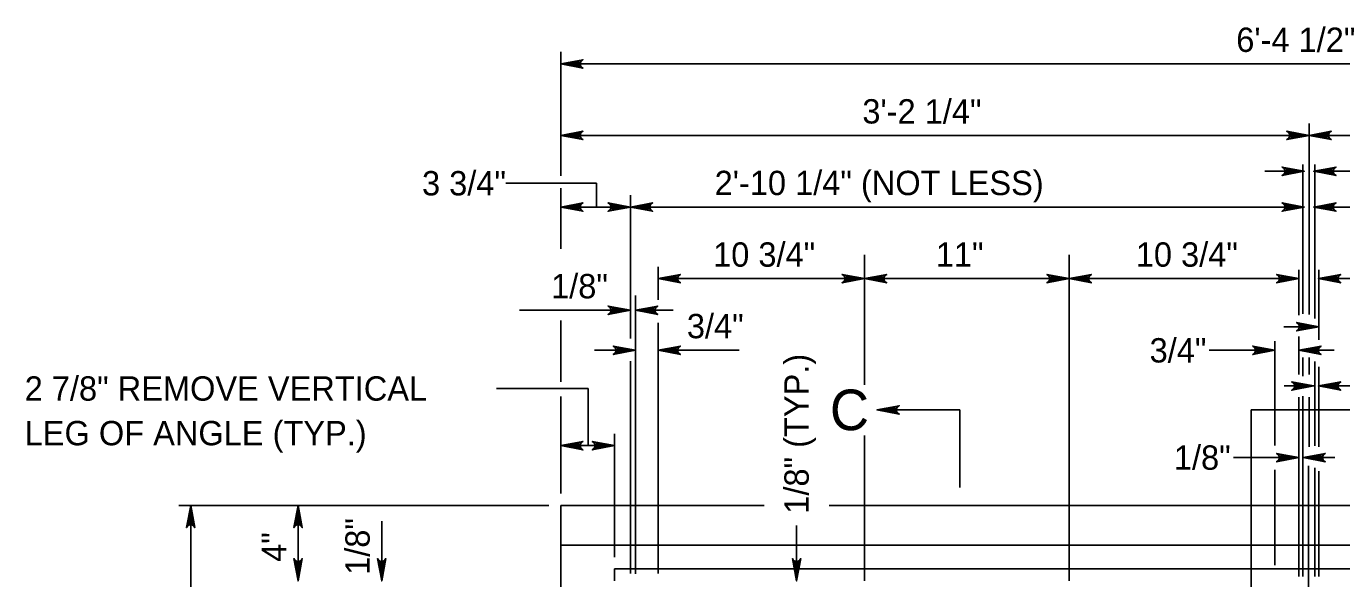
# Model space of a CAD drawing. Extents: x 0.7 to 7.67, y -7.49 to 2.47.
# Drawn here: x 0.71 to 3.951, y 1.111 to 2.473 of the extents above; entities that cross this region are included whole.
import ezdxf

# ---------------------------------------------------------------- set-up
doc = ezdxf.new("R2010")
doc.units = 0
for name, color, linetype in [('DETL-DIMS', 7, 'Continuous'), ('DETL-LINE', 7, 'Continuous'), ('DETL-NOTE', 7, 'Continuous'), ('DETL-TITL', 7, 'Continuous')]:
    doc.layers.add(name, color=color, linetype=linetype)

msp = doc.modelspace()

# ---------------------------------------------------------------- linework, layer by layer
at = {"layer": 'DETL-DIMS'}
for p, q in [((2.0269, 2.1048), (2.0269, 2.4099)), ((2.0269, 2.3805), (5.7132, 2.3805)), ((3.8707, 2.204), (2.0269, 2.204)), ((3.8707, 1.7626), (3.8707, 2.2334)), ((3.8707, 2.204), (5.7132, 2.204)), ((3.7617, 2.1158), (3.8554, 2.1158)), ((3.8554, 1.7642), (3.8554, 2.1326)), ((3.8848, 1.7527), (3.8848, 2.1326)), ((3.8848, 2.1158), (4.0025, 2.1158)), ((2.1153, 2.0862), (1.8921, 2.0862)), ((2.1153, 2.0262), (2.1153, 2.0862)), ((2.0269, 1.9249), (2.0269, 2.0739)), ((2.1985, 1.7038), (2.1985, 2.0569)), ((2.0269, 2.0275), (3.8554, 2.0275)), ((3.8848, 2.0275), (5.7132, 2.0275)), ((2.2671, 1.7984), (2.2671, 1.8805)), ((2.7751, 1.5889), (2.7751, 1.9099)), ((3.2796, 1.106), (3.2796, 1.9099)), ((2.7751, 1.8511), (2.2671, 1.8511)), ((2.7751, 1.8511), (3.2796, 1.8511)), ((3.2796, 1.8511), (3.8455, 1.8511)), ((3.8455, 1.7609), (3.8455, 1.8726)), ((3.8946, 1.7004), (3.8946, 1.8726)), ((4.4594, 1.8511), (3.8946, 1.8511)), ((2.2112, 1.1236), (2.2112, 1.8097)), ((2.1985, 1.7731), (1.9254, 1.7731)), ((2.2112, 1.7731), (2.3039, 1.7731)), ((2.0269, 1.597), (2.0269, 1.7478)), ((2.2671, 1.1245), (2.2671, 1.7422)), ((3.8946, 1.7325), (3.8087, 1.7325)), ((3.7867, 1.4396), (3.7867, 1.6972)), ((3.8455, 1.6151), (3.8455, 1.7086)), ((2.1101, 1.6746), (2.2112, 1.6746)), ((2.2671, 1.6746), (2.4669, 1.6748)), ((3.7867, 1.6743), (3.6247, 1.6743)), ((3.8455, 1.6743), (3.9328, 1.6743)), ((3.8554, 1.6109), (3.8554, 1.6563)), ((3.8707, 1.6151), (3.8707, 1.6563)), ((2.1985, 1.1245), (2.1985, 1.6476)), ((3.8848, 1.4386), (3.8848, 1.6465)), ((3.8946, 1.4365), (3.8946, 1.6334)), ((2.0942, 1.5802), (1.8688, 1.5802)), ((2.0269, 1.3217), (2.0269, 1.5605)), ((2.0942, 1.4389), (2.0942, 1.5802)), ((3.8095, 1.5864), (3.8828, 1.5864)), ((3.8455, 1.1166), (3.8455, 1.559)), ((3.8554, 1.1166), (3.8554, 1.5611)), ((3.8707, 1.4365), (3.8707, 1.559)), ((3.8939, 1.5864), (4.0308, 1.5864)), ((2.8061, 1.5275), (3.0104, 1.5275)), ((3.0104, 1.3364), (3.0104, 1.5275)), ((2.1593, 1.1648), (2.1593, 1.4687)), ((2.7751, 1.106), (2.7751, 1.4641)), ((2.0269, 1.4393), (2.1593, 1.4393)), ((3.8455, 1.1166), (3.8455, 1.4302)), ((3.6845, 1.4099), (3.8454, 1.4099)), ((3.8558, 1.4099), (3.9345, 1.4099)), ((3.7867, 1.1446), (3.7867, 1.3794)), ((3.8693, 1.3894), (3.8693, -0.7657)), ((3.8848, 1.1166), (3.8848, 1.3846)), ((3.8946, 1.1166), (3.8946, 1.3762)), ((1.9975, 1.2922), (1.0858, 1.2922)), ((1.1152, -0.5901), (1.1152, 1.2922)), ((1.3799, 1.106), (1.3799, 1.2922)), ((1.5858, 1.106), (1.5858, 1.253)), ((2.608, 1.2422), (2.608, 1.106))]:
    msp.add_line(p, q, dxfattribs=at)
for points in [[(2.0269, 2.3805), (2.0818, 2.3908), (2.0775, 2.3878), (2.0754, 2.3842), (2.0747, 2.3805), (2.0754, 2.3768), (2.0775, 2.3731), (2.0818, 2.3702), (2.0269, 2.3805), (2.0775, 2.3731), (2.0754, 2.3768), (2.0269, 2.3805), (2.0747, 2.3805), (2.0754, 2.3842), (2.0269, 2.3805), (2.0775, 2.3878)], [(2.0269, 2.204), (2.0818, 2.2143), (2.0775, 2.2114), (2.0754, 2.2077), (2.0747, 2.204), (2.0754, 2.2003), (2.0775, 2.1967), (2.0818, 2.1937), (2.0269, 2.204), (2.0775, 2.1967), (2.0754, 2.2003), (2.0269, 2.204), (2.0747, 2.204), (2.0754, 2.2077), (2.0269, 2.204), (2.0775, 2.2114)], [(3.8707, 2.204), (3.8159, 2.1937), (3.8201, 2.1967), (3.8223, 2.2003), (3.8229, 2.204), (3.8223, 2.2077), (3.8201, 2.2114), (3.8159, 2.2143), (3.8707, 2.204), (3.8201, 2.2114), (3.8223, 2.2077), (3.8707, 2.204), (3.8229, 2.204), (3.8223, 2.2003), (3.8707, 2.204), (3.8201, 2.1967)], [(3.8707, 2.204), (3.9255, 2.1937), (3.9213, 2.1967), (3.9191, 2.2003), (3.9185, 2.204), (3.9191, 2.2077), (3.9213, 2.2114), (3.9255, 2.2143), (3.8707, 2.204), (3.9213, 2.2114), (3.9191, 2.2077), (3.8707, 2.204), (3.9185, 2.204), (3.9191, 2.2003), (3.8707, 2.204), (3.9213, 2.1967)], [(3.859, 2.1158), (3.8042, 2.1055), (3.8084, 2.1084), (3.8106, 2.1121), (3.8112, 2.1158), (3.8106, 2.1195), (3.8084, 2.1231), (3.8042, 2.1261), (3.859, 2.1158), (3.8084, 2.1231), (3.8106, 2.1195), (3.859, 2.1158), (3.8112, 2.1158), (3.8106, 2.1121), (3.859, 2.1158), (3.8084, 2.1084)], [(3.8823, 2.1158), (3.9371, 2.1261), (3.9329, 2.1231), (3.9307, 2.1195), (3.9301, 2.1158), (3.9307, 2.1121), (3.9329, 2.1084), (3.9371, 2.1055), (3.8823, 2.1158), (3.9329, 2.1084), (3.9307, 2.1121), (3.8823, 2.1158), (3.9301, 2.1158), (3.9307, 2.1195), (3.8823, 2.1158), (3.9329, 2.1231)], [(2.0269, 2.0275), (2.0818, 2.0378), (2.0775, 2.0349), (2.0754, 2.0312), (2.0747, 2.0275), (2.0754, 2.0239), (2.0775, 2.0202), (2.0818, 2.0173), (2.0269, 2.0275), (2.0775, 2.0202), (2.0754, 2.0239), (2.0269, 2.0275), (2.0747, 2.0275), (2.0754, 2.0312), (2.0269, 2.0275), (2.0775, 2.0349)], [(2.1985, 2.0275), (2.1437, 2.0173), (2.1479, 2.0202), (2.1501, 2.0239), (2.1507, 2.0275), (2.1501, 2.0312), (2.1479, 2.0349), (2.1437, 2.0378), (2.1985, 2.0275), (2.1479, 2.0349), (2.1501, 2.0312), (2.1985, 2.0275), (2.1507, 2.0275), (2.1501, 2.0239), (2.1985, 2.0275), (2.1479, 2.0202)], [(2.1985, 2.0275), (2.2533, 2.0173), (2.2491, 2.0202), (2.2469, 2.0239), (2.2463, 2.0275), (2.2469, 2.0312), (2.2491, 2.0349), (2.2533, 2.0378), (2.1985, 2.0275), (2.2491, 2.0349), (2.2469, 2.0312), (2.1985, 2.0275), (2.2463, 2.0275), (2.2469, 2.0239), (2.1985, 2.0275), (2.2491, 2.0202)], [(3.859, 2.0275), (3.8042, 2.0173), (3.8084, 2.0202), (3.8106, 2.0239), (3.8112, 2.0275), (3.8106, 2.0312), (3.8084, 2.0349), (3.8042, 2.0378), (3.859, 2.0275), (3.8084, 2.0349), (3.8106, 2.0312), (3.859, 2.0275), (3.8112, 2.0275), (3.8106, 2.0239), (3.859, 2.0275), (3.8084, 2.0202)], [(3.8823, 2.0275), (3.9371, 2.0378), (3.9329, 2.0349), (3.9307, 2.0312), (3.9301, 2.0275), (3.9307, 2.0239), (3.9329, 2.0202), (3.9371, 2.0173), (3.8823, 2.0275), (3.9329, 2.0202), (3.9307, 2.0239), (3.8823, 2.0275), (3.9301, 2.0275), (3.9307, 2.0312), (3.8823, 2.0275), (3.9329, 2.0349)], [(2.2671, 1.8511), (2.322, 1.8613), (2.3177, 1.8584), (2.3156, 1.8547), (2.3149, 1.8511), (2.3156, 1.8474), (2.3177, 1.8437), (2.322, 1.8408), (2.2671, 1.8511), (2.3177, 1.8437), (2.3156, 1.8474), (2.2671, 1.8511), (2.3149, 1.8511), (2.3156, 1.8547), (2.2671, 1.8511), (2.3177, 1.8584)], [(2.7751, 1.8511), (2.7203, 1.8408), (2.7245, 1.8437), (2.7267, 1.8474), (2.7273, 1.8511), (2.7267, 1.8547), (2.7245, 1.8584), (2.7203, 1.8613), (2.7751, 1.8511), (2.7245, 1.8584), (2.7267, 1.8547), (2.7751, 1.8511), (2.7273, 1.8511), (2.7267, 1.8474), (2.7751, 1.8511), (2.7245, 1.8437)], [(2.7751, 1.8511), (2.83, 1.8408), (2.8257, 1.8437), (2.8236, 1.8474), (2.8229, 1.8511), (2.8236, 1.8547), (2.8257, 1.8584), (2.83, 1.8613), (2.7751, 1.8511), (2.8257, 1.8584), (2.8236, 1.8547), (2.7751, 1.8511), (2.8229, 1.8511), (2.8236, 1.8474), (2.7751, 1.8511), (2.8257, 1.8437)], [(3.2796, 1.8511), (3.2248, 1.8408), (3.229, 1.8437), (3.2312, 1.8474), (3.2318, 1.8511), (3.2312, 1.8547), (3.229, 1.8584), (3.2248, 1.8613), (3.2796, 1.8511), (3.229, 1.8584), (3.2312, 1.8547), (3.2796, 1.8511), (3.2318, 1.8511), (3.2312, 1.8474), (3.2796, 1.8511), (3.229, 1.8437)], [(3.2796, 1.8511), (3.3345, 1.8408), (3.3302, 1.8437), (3.3281, 1.8474), (3.3274, 1.8511), (3.3281, 1.8547), (3.3302, 1.8584), (3.3345, 1.8613), (3.2796, 1.8511), (3.3302, 1.8584), (3.3281, 1.8547), (3.2796, 1.8511), (3.3274, 1.8511), (3.3281, 1.8474), (3.2796, 1.8511), (3.3302, 1.8437)], [(3.8456, 1.8511), (3.7907, 1.8408), (3.795, 1.8437), (3.7971, 1.8474), (3.7978, 1.8511), (3.7971, 1.8547), (3.795, 1.8584), (3.7907, 1.8613), (3.8456, 1.8511), (3.795, 1.8584), (3.7971, 1.8547), (3.8456, 1.8511), (3.7978, 1.8511), (3.7971, 1.8474), (3.8456, 1.8511), (3.795, 1.8437)], [(3.8939, 1.8511), (3.9487, 1.8613), (3.9445, 1.8584), (3.9423, 1.8547), (3.9417, 1.8511), (3.9423, 1.8474), (3.9445, 1.8437), (3.9487, 1.8408), (3.8939, 1.8511), (3.9445, 1.8437), (3.9423, 1.8474), (3.8939, 1.8511), (3.9417, 1.8511), (3.9423, 1.8547), (3.8939, 1.8511), (3.9445, 1.8584)], [(2.1985, 1.7731), (2.1437, 1.7628), (2.1479, 1.7658), (2.1501, 1.7694), (2.1507, 1.7731), (2.1501, 1.7768), (2.1479, 1.7805), (2.1437, 1.7834), (2.1985, 1.7731), (2.1479, 1.7805), (2.1501, 1.7768), (2.1985, 1.7731), (2.1507, 1.7731), (2.1501, 1.7694), (2.1985, 1.7731), (2.1479, 1.7658)], [(2.2112, 1.7731), (2.2661, 1.7834), (2.2618, 1.7805), (2.2597, 1.7768), (2.259, 1.7731), (2.2597, 1.7694), (2.2618, 1.7658), (2.2661, 1.7628), (2.2112, 1.7731), (2.2618, 1.7658), (2.2597, 1.7694), (2.2112, 1.7731), (2.259, 1.7731), (2.2597, 1.7768), (2.2112, 1.7731), (2.2618, 1.7805)], [(3.8946, 1.7325), (3.8398, 1.7223), (3.844, 1.7252), (3.8462, 1.7289), (3.8468, 1.7325), (3.8462, 1.7362), (3.844, 1.7399), (3.8398, 1.7428), (3.8946, 1.7325), (3.844, 1.7399), (3.8462, 1.7362), (3.8946, 1.7325), (3.8468, 1.7325), (3.8462, 1.7289), (3.8946, 1.7325), (3.844, 1.7252)], [(2.2112, 1.6746), (2.1564, 1.6643), (2.1606, 1.6672), (2.1628, 1.6709), (2.1635, 1.6746), (2.1628, 1.6783), (2.1606, 1.6819), (2.1564, 1.6849), (2.2112, 1.6746), (2.1606, 1.6819), (2.1628, 1.6783), (2.2112, 1.6746), (2.1635, 1.6746), (2.1628, 1.6709), (2.2112, 1.6746), (2.1606, 1.6672)], [(2.2671, 1.6746), (2.322, 1.6849), (2.3177, 1.6819), (2.3156, 1.6783), (2.3149, 1.6746), (2.3156, 1.6709), (2.3177, 1.6672), (2.322, 1.6643), (2.2671, 1.6746), (2.3177, 1.6672), (2.3156, 1.6709), (2.2671, 1.6746), (2.3149, 1.6746), (2.3156, 1.6783), (2.2671, 1.6746), (2.3177, 1.6819)], [(3.7867, 1.6743), (3.7319, 1.664), (3.7361, 1.6669), (3.7383, 1.6706), (3.7389, 1.6743), (3.7383, 1.678), (3.7361, 1.6816), (3.7319, 1.6846), (3.7867, 1.6743), (3.7361, 1.6816), (3.7383, 1.678), (3.7867, 1.6743), (3.7389, 1.6743), (3.7383, 1.6706), (3.7867, 1.6743), (3.7361, 1.6669)], [(3.8455, 1.6743), (3.9004, 1.6846), (3.8961, 1.6816), (3.894, 1.678), (3.8933, 1.6743), (3.894, 1.6706), (3.8961, 1.6669), (3.9004, 1.664), (3.8455, 1.6743), (3.8961, 1.6669), (3.894, 1.6706), (3.8455, 1.6743), (3.8933, 1.6743), (3.894, 1.678), (3.8455, 1.6743), (3.8961, 1.6816)], [(3.8828, 1.5864), (3.828, 1.5761), (3.8322, 1.579), (3.8344, 1.5827), (3.835, 1.5864), (3.8344, 1.59), (3.8322, 1.5937), (3.828, 1.5966), (3.8828, 1.5864), (3.8322, 1.5937), (3.8344, 1.59), (3.8828, 1.5864), (3.835, 1.5864), (3.8344, 1.5827), (3.8828, 1.5864), (3.8322, 1.579)], [(3.8939, 1.5864), (3.9487, 1.5966), (3.9445, 1.5937), (3.9423, 1.59), (3.9417, 1.5864), (3.9423, 1.5827), (3.9445, 1.579), (3.9487, 1.5761), (3.8939, 1.5864), (3.9445, 1.579), (3.9423, 1.5827), (3.8939, 1.5864), (3.9417, 1.5864), (3.9423, 1.59), (3.8939, 1.5864), (3.9445, 1.5937)], [(2.8061, 1.5275), (2.8609, 1.5378), (2.8567, 1.5349), (2.8545, 1.5312), (2.8539, 1.5275), (2.8545, 1.5239), (2.8567, 1.5202), (2.8609, 1.5173), (2.8061, 1.5275), (2.8567, 1.5202), (2.8545, 1.5239), (2.8061, 1.5275), (2.8539, 1.5275), (2.8545, 1.5312), (2.8061, 1.5275), (2.8567, 1.5349)], [(2.0269, 1.4393), (2.0818, 1.4496), (2.0775, 1.4467), (2.0754, 1.443), (2.0747, 1.4393), (2.0754, 1.4356), (2.0775, 1.4319), (2.0818, 1.429), (2.0269, 1.4393), (2.0775, 1.4319), (2.0754, 1.4356), (2.0269, 1.4393), (2.0747, 1.4393), (2.0754, 1.443), (2.0269, 1.4393), (2.0775, 1.4467)], [(2.1593, 1.4393), (2.1045, 1.429), (2.1087, 1.4319), (2.1109, 1.4356), (2.1115, 1.4393), (2.1109, 1.443), (2.1087, 1.4467), (2.1045, 1.4496), (2.1593, 1.4393), (2.1087, 1.4467), (2.1109, 1.443), (2.1593, 1.4393), (2.1115, 1.4393), (2.1109, 1.4356), (2.1593, 1.4393), (2.1087, 1.4319)], [(3.8454, 1.4099), (3.7906, 1.3996), (3.7948, 1.4025), (3.797, 1.4062), (3.7976, 1.4099), (3.797, 1.4136), (3.7948, 1.4172), (3.7906, 1.4202), (3.8454, 1.4099), (3.7948, 1.4172), (3.797, 1.4136), (3.8454, 1.4099), (3.7976, 1.4099), (3.797, 1.4062), (3.8454, 1.4099), (3.7948, 1.4025)], [(3.8558, 1.4099), (3.9106, 1.4202), (3.9064, 1.4172), (3.9042, 1.4136), (3.9036, 1.4099), (3.9042, 1.4062), (3.9064, 1.4025), (3.9106, 1.3996), (3.8558, 1.4099), (3.9064, 1.4025), (3.9042, 1.4062), (3.8558, 1.4099), (3.9036, 1.4099), (3.9042, 1.4136), (3.8558, 1.4099), (3.9064, 1.4172)], [(1.1152, 1.2922), (1.1254, 1.2374), (1.1225, 1.2416), (1.1188, 1.2438), (1.1152, 1.2444), (1.1115, 1.2438), (1.1078, 1.2416), (1.1049, 1.2374), (1.1152, 1.2922), (1.1078, 1.2416), (1.1115, 1.2438), (1.1152, 1.2922), (1.1152, 1.2444), (1.1188, 1.2438), (1.1152, 1.2922), (1.1225, 1.2416)], [(1.3799, 1.2922), (1.3902, 1.2374), (1.3872, 1.2416), (1.3835, 1.2438), (1.3799, 1.2444), (1.3762, 1.2438), (1.3725, 1.2416), (1.3696, 1.2374), (1.3799, 1.2922), (1.3725, 1.2416), (1.3762, 1.2438), (1.3799, 1.2922), (1.3799, 1.2444), (1.3835, 1.2438), (1.3799, 1.2922), (1.3872, 1.2416)], [(1.3799, 1.106), (1.3902, 1.1608), (1.3872, 1.1566), (1.3835, 1.1544), (1.3799, 1.1538), (1.3762, 1.1544), (1.3725, 1.1566), (1.3696, 1.1608), (1.3799, 1.106), (1.3725, 1.1566), (1.3762, 1.1544), (1.3799, 1.106), (1.3799, 1.1538), (1.3835, 1.1544), (1.3799, 1.106), (1.3872, 1.1566)], [(1.5858, 1.106), (1.5755, 1.1608), (1.5784, 1.1566), (1.5821, 1.1544), (1.5858, 1.1538), (1.5894, 1.1544), (1.5931, 1.1566), (1.596, 1.1608), (1.5858, 1.106), (1.5931, 1.1566), (1.5894, 1.1544), (1.5858, 1.106), (1.5858, 1.1538), (1.5821, 1.1544), (1.5858, 1.106), (1.5784, 1.1566)], [(2.608, 1.106), (2.5977, 1.1608), (2.6007, 1.1566), (2.6043, 1.1544), (2.608, 1.1538), (2.6117, 1.1544), (2.6154, 1.1566), (2.6183, 1.1608), (2.608, 1.106), (2.6154, 1.1566), (2.6117, 1.1544), (2.608, 1.106), (2.608, 1.1538), (2.6043, 1.1544), (2.608, 1.106), (2.6007, 1.1566)]]:
    msp.add_lwpolyline(points, dxfattribs=at)
at = {"layer": 'DETL-LINE'}
for p, q in [((3.7279, -0.7666), (3.7279, 1.5275)), ((3.7279, 1.5275), (4.0122, 1.5275)), ((2.0269, 0.9942), (2.0269, 1.2922)), ((2.0269, 1.2922), (2.5279, 1.2922)), ((2.6886, 1.2922), (5.7132, 1.2922)), ((2.0269, 1.1942), (5.7132, 1.1942)), ((2.1593, 1.1354), (5.5809, 1.1354)), ((2.1593, 1.106), (2.1593, 1.1354))]:
    msp.add_line(p, q, dxfattribs=at)

# ---------------------------------------------------------------- texts
at = {"layer": 'DETL-NOTE'}
for s, p in [('6\'-4 1/2"', (3.6913, 2.4099)), ('3\'-2 1/4"', (2.7701, 2.2334)), ('3 3/4"', (1.6852, 2.0562)), ('2\'-10 1/4" (NOT LESS)', (2.4061, 2.0569)), ('10 3/4"', (2.4024, 1.8805)), ('11"', (2.951, 1.8805)), ('10 3/4"', (3.4438, 1.8805)), ('1/8"', (2.0032, 1.8025)), ('3/4"', (2.3377, 1.7041)), ('3/4"', (3.4778, 1.6443)), ('2 7/8" REMOVE VERTICAL', (0.7062, 1.5502)), ('LEG OF ANGLE (TYP.)', (0.7062, 1.4402)), ('1/8"', (3.5376, 1.3799))]:
    msp.add_text(s, height=0.06, dxfattribs=at).set_placement(p)
for s, p in [('1/8" (TYP.)', (2.638, 1.2716)), ('1/8"', (1.5563, 1.1208)), ('4"', (1.3505, 1.1528))]:
    msp.add_text(s, height=0.06, rotation=90, dxfattribs=at).set_placement(p)
at = {"layer": 'DETL-TITL'}
msp.add_text('C', height=0.1, dxfattribs=at).set_placement((2.6901, 1.4775))

doc.saveas('drawing.dxf')
